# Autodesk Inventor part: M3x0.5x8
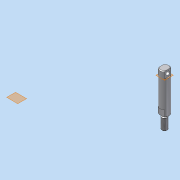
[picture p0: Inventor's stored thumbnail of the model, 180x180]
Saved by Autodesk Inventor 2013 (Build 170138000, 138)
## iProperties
Company: 한국ATC센터
Created: 2009-02
Part Number: M3x0.5x8
Document SubType Name: Modeling
Designer: KYOUNG IL JANG
Density: 2.71 g/cm^3
Material: 알루미늄-6061
Mass: 23.7345 g
Surface Area: 33.7774 cm^2
Volume: 8.75813 cm^3
Vendor: CBT Solutions
Author: KYOUNG IL JANG
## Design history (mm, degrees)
node "작업 평면1"
sketch "스케치1"
  geometry: L1 (126.442, 94.902)-(135.988, 94.902); L2 (135.988, 94.902)-(135.988, 85.356); L3 (135.988, 85.356)-(126.442, 85.356); L4 (126.442, 85.356)-(126.442, 94.902); A1 r 6.75 centre (131.215, 90.129) between (126.442, 94.902) and (126.442, 85.356); A2 r 6.75 centre (131.215, 90.129) between (135.988, 94.902) and (126.442, 94.902); A3 r 6.75 centre (131.215, 90.129) between (135.988, 85.356) and (135.988, 94.902); A4 r 6.75 centre (131.215, 90.129) between (126.442, 85.356) and (135.988, 85.356); 2 further points
  constraints: 8 end point, 8 point on circle, 4 centre point, 2 coincident, 1 horizontal, 9 other
  dimensions: "d0" = 13.5 diameter of A1
extrude "돌출1" new body sketch "스케치1" distance "d1" = 60; taper "d2" = 0 deg
sketch "스케치2"
  geometry: C1 r 4 at (0, 0); 1 further point
  constraints: 1 centre point, 1 coincident
  dimensions: "d3" = 8 diameter of C1
extrude "돌출2" join sketch "스케치2" distance "d4" = 20; taper "d5" = 0 deg
sketch "스케치3"
  geometry: C1 r 4 at (0, 0) reference; C2 r 3 at (0, 0); 1 further point
  constraints: 1 centre point
  dimensions: "d6" = 1 radial gap between concentric circles of C1 C2
extrude "돌출3" cut sketch "스케치3" distance "d7" = 2; taper "d8" = 0 deg
chamfer "모따기1" distance "d9" = 1; stored, may be unused: second distance "d10" = 2, angle "d11" = 45 deg
feature "스레드1" dims "d12" = 10, "d13" = 0
chamfer "모따기2" distance "d14" = 1; stored, may be unused: second distance "d15" = 2, angle "d16" = 45 deg
extrude "돌출4" cut sketch "스케치1" distance "d18" = 10; taper "d19" = 0 deg
node "작업 평면2"
chamfer "모따기3" distance "d23" = 1; stored, may be unused: second distance "d24" = 2, angle "d25" = 45 deg
extrude "돌출5" cut sketch "스케치1" stored distance "d21" = 10; taper "d22" = 0 deg
sketch "스케치4"
  geometry: L1 (-10, 7.979)-(-10, 1.567) reference; 2 further points
  constraints: 1 horizontal alignment
  dimensions: "d26" = 5 distance from line of point (-5, 4.773) L1
hole "구멍1" sketch "스케치4" at (-5, 4.773) diameter "d27" = 5.5; stored, may be unused: countersink angle "d31" = 90 deg, drill point angle "d33" = 118 deg; dims "d28" = 6, "d29" = 4, "d30" = 2, "d32" = 8
node "솔리드1"
